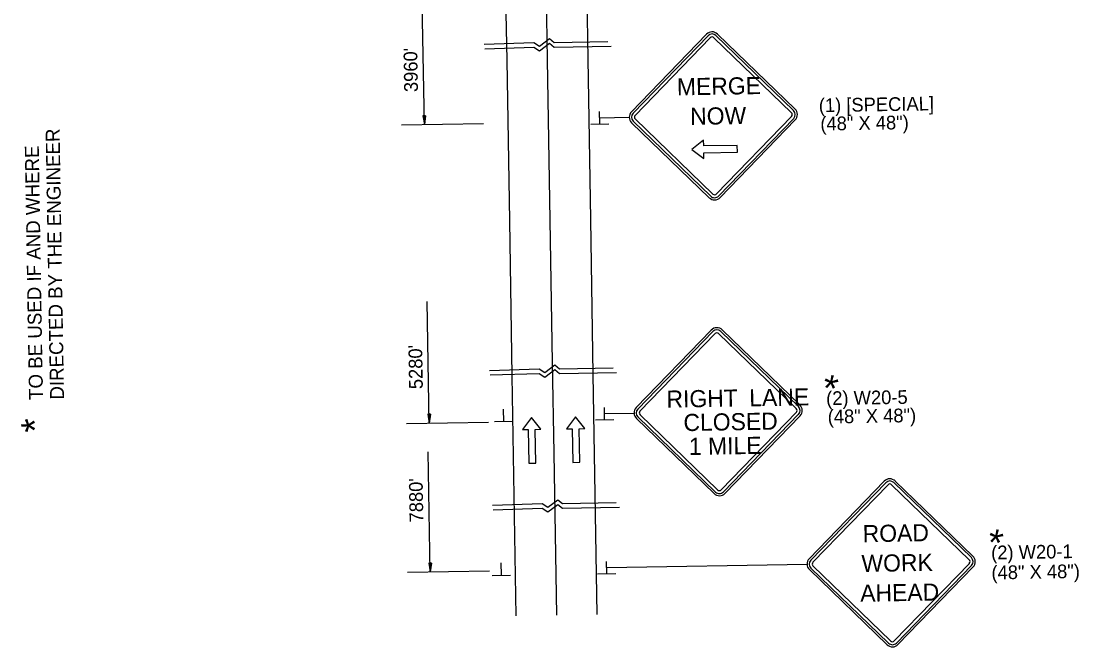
# Model space of a CAD drawing. Extents: x 1676639 to 1677883, y 226447 to 231777.
# Drawn here: x 1676908.3 to 1677371.1, y 228417.4 to 228691.4 of the extents above; entities that cross this region are included whole.
import ezdxf

# ---------------------------------------------------------------- set-up
doc = ezdxf.new("R2010")
doc.units = 0
for name, color, linetype in [('Default', 7, 'Continuous'), ('P_TC_Signs_Temporary', 7, 'Continuous'), ('R_Annotation', 7, 'Continuous'), ('R_MOT', 7, 'Continuous')]:
    doc.layers.add(name, color=color, linetype=linetype)

msp = doc.modelspace()

# ---------------------------------------------------------------- linework, layer by layer
at = {"layer": 'Default'}
for p, q in [((1677156.36, 228674.93), (1677155.09, 228751.27)), ((1677120.9, 228674.34), (1677119.65, 228749.75)), ((1677138.63, 228674.64), (1677137.37, 228750.51)), ((1677084.73, 228646.15), (1677083.84, 228699.37)), ((1677122.07, 228603.97), (1677120.9, 228674.34)), ((1677139.8, 228604.26), (1677138.63, 228674.64)), ((1677157.53, 228604.56), (1677156.36, 228674.93)), ((1677085.24, 228649.98), (1677084.09, 228649.97)), ((1677084.09, 228649.97), (1677084.73, 228646.15)), ((1677084.19, 228649.97), (1677084.72, 228646.79)), ((1677084.28, 228649.97), (1677084.71, 228647.45)), ((1677084.38, 228649.97), (1677084.7, 228648.08)), ((1677084.48, 228649.97), (1677084.68, 228648.73)), ((1677084.57, 228649.97), (1677084.67, 228649.37)), ((1677084.75, 228649.98), (1677084.67, 228649.37)), ((1677084.85, 228649.98), (1677084.68, 228648.73)), ((1677084.95, 228649.98), (1677084.7, 228648.08)), ((1677085.04, 228649.98), (1677084.71, 228647.45)), ((1677085.14, 228649.98), (1677084.72, 228646.79)), ((1677085.24, 228649.98), (1677084.73, 228646.15)), ((1677161.52, 228646.37), (1677161.43, 228651.81)), ((1677074.74, 228645.98), (1677110.65, 228646.58)), ((1677165.49, 228646.32), (1677157.51, 228646.18)), ((1677123.19, 228536.03), (1677122.07, 228603.97)), ((1677140.83, 228541.87), (1677139.8, 228604.26)), ((1677158.65, 228536.67), (1677157.53, 228604.56)), ((1677086.89, 228515.44), (1677086.01, 228568.67)), ((1677141.49, 228502.17), (1677140.83, 228541.87)), ((1677123.77, 228501.1), (1677123.19, 228536.03)), ((1677159.23, 228501.74), (1677158.65, 228536.67)), ((1677119.49, 228516.1), (1677119.4, 228521.55)), ((1677163.61, 228516.83), (1677163.52, 228522.28)), ((1677076.91, 228515.28), (1677112.82, 228515.87)), ((1677087.4, 228519.28), (1677086.26, 228519.26)), ((1677086.26, 228519.26), (1677086.89, 228515.44)), ((1677086.35, 228519.26), (1677086.88, 228516.08)), ((1677086.45, 228519.26), (1677086.87, 228516.74)), ((1677086.55, 228519.26), (1677086.86, 228517.38)), ((1677086.64, 228519.26), (1677086.85, 228518.03)), ((1677086.74, 228519.27), (1677086.84, 228518.66)), ((1677086.92, 228519.27), (1677086.84, 228518.66)), ((1677087.02, 228519.27), (1677086.85, 228518.03)), ((1677087.12, 228519.27), (1677086.86, 228517.38)), ((1677087.21, 228519.27), (1677086.87, 228516.74)), ((1677087.31, 228519.28), (1677086.88, 228516.08)), ((1677087.4, 228519.28), (1677086.89, 228515.44)), ((1677123.46, 228516.05), (1677115.48, 228515.92)), ((1677167.58, 228516.78), (1677159.6, 228516.65)), ((1677087.29, 228450.25), (1677086.42, 228502.87)), ((1677124.94, 228430.96), (1677123.77, 228501.1)), ((1677142.67, 228431.25), (1677141.49, 228502.17)), ((1677160.4, 228431.55), (1677159.23, 228501.74)), ((1677164.56, 228449.43), (1677164.47, 228454.87)), ((1677077.31, 228450.08), (1677113.22, 228450.68)), ((1677087.81, 228454.08), (1677086.66, 228454.06)), ((1677086.66, 228454.06), (1677087.29, 228450.25)), ((1677086.75, 228454.06), (1677087.28, 228450.89)), ((1677086.85, 228454.06), (1677087.27, 228451.54)), ((1677086.95, 228454.07), (1677087.26, 228452.18)), ((1677087.04, 228454.07), (1677087.25, 228452.83)), ((1677087.14, 228454.07), (1677087.24, 228453.47)), ((1677087.32, 228454.07), (1677087.24, 228453.47)), ((1677087.42, 228454.07), (1677087.25, 228452.83)), ((1677087.52, 228454.08), (1677087.26, 228452.18)), ((1677087.61, 228454.08), (1677087.27, 228451.54)), ((1677087.71, 228454.08), (1677087.28, 228450.89)), ((1677087.81, 228454.08), (1677087.29, 228450.25)), ((1677118.48, 228448.76), (1677118.39, 228454.21)), ((1677122.45, 228448.71), (1677114.47, 228448.58)), ((1677168.53, 228449.37), (1677160.56, 228449.24))]:
    msp.add_line(p, q, dxfattribs=at)
for points in [[(1677110.9, 228681.36), (1677132.63, 228682.05), (1677135.12, 228680.44), (1677139.48, 228683.74), (1677141.55, 228682.07), (1677164.97, 228682.46)], [(1677111.13, 228679.33), (1677132.58, 228680.01), (1677135.07, 228678.4), (1677139.43, 228681.7), (1677141.5, 228680.03), (1677166.44, 228680.44)], [(1677113.27, 228538.49), (1677135, 228539.18), (1677137.49, 228537.57), (1677141.85, 228540.87), (1677143.92, 228539.2), (1677167.34, 228539.59)], [(1677113.5, 228536.46), (1677134.95, 228537.14), (1677137.44, 228535.53), (1677141.8, 228538.83), (1677143.86, 228537.16), (1677168.81, 228537.57)], [(1677114.59, 228479.49), (1677136.31, 228480.18), (1677138.81, 228478.57), (1677143.17, 228481.87), (1677145.23, 228480.2), (1677168.66, 228480.59)], [(1677114.82, 228477.46), (1677136.26, 228478.15), (1677138.75, 228476.53), (1677143.12, 228479.83), (1677145.18, 228478.17), (1677170.12, 228478.57)]]:
    msp.add_lwpolyline(points, dxfattribs=at)
at = {"layer": 'P_TC_Signs_Temporary'}
for p, q in [((1677175.35, 228651.71), (1677208.21, 228685.67)), ((1677176.03, 228651.06), (1677208.88, 228685.02)), ((1677176.97, 228650.14), (1677209.82, 228684.1)), ((1677211.41, 228684.13), (1677245.37, 228651.28)), ((1677212.33, 228685.07), (1677246.29, 228652.22)), ((1677212.98, 228685.75), (1677246.94, 228652.89)), ((1677245.4, 228649.69), (1677212.55, 228615.73)), ((1677209.39, 228614.08), (1677175.43, 228646.93)), ((1677210.04, 228614.76), (1677176.08, 228647.61)), ((1677210.96, 228615.7), (1677177, 228648.55)), ((1677246.34, 228648.77), (1677213.49, 228614.81)), ((1677247.02, 228648.12), (1677214.16, 228614.16)), ((1677177.44, 228522.17), (1677210.29, 228556.13)), ((1677178.12, 228521.52), (1677210.97, 228555.48)), ((1677179.06, 228520.61), (1677211.91, 228554.57)), ((1677213.5, 228554.59), (1677247.46, 228521.74)), ((1677214.42, 228555.54), (1677248.38, 228522.69)), ((1677215.07, 228556.21), (1677249.03, 228523.36)), ((1677247.49, 228520.15), (1677214.64, 228486.19)), ((1677211.48, 228484.55), (1677177.52, 228517.4)), ((1677212.13, 228485.22), (1677178.17, 228518.07)), ((1677213.05, 228486.16), (1677179.09, 228519.02)), ((1677248.43, 228519.24), (1677215.58, 228485.28)), ((1677249.11, 228518.59), (1677216.25, 228484.63)), ((1677253.12, 228456.01), (1677285.98, 228489.97)), ((1677253.8, 228455.35), (1677286.65, 228489.31)), ((1677254.74, 228454.44), (1677287.59, 228488.4)), ((1677289.18, 228488.43), (1677323.14, 228455.57)), ((1677290.1, 228489.37), (1677324.06, 228456.52)), ((1677290.75, 228490.04), (1677324.71, 228457.19)), ((1677287.16, 228418.38), (1677253.2, 228451.23)), ((1677287.82, 228419.05), (1677253.86, 228451.91)), ((1677288.73, 228420), (1677254.77, 228452.85)), ((1677323.17, 228453.98), (1677290.32, 228420.02)), ((1677324.11, 228453.07), (1677291.26, 228419.11)), ((1677324.79, 228452.42), (1677291.94, 228418.46))]:
    msp.add_line(p, q, dxfattribs=at)
for centre, radius, start, end in [((1677210.63, 228683.32), 3.38, 45.9497, 135.9497), ((1677210.63, 228683.32), 2.44, 45.9497, 135.9497), ((1677210.63, 228683.32), 1.13, 45.9497, 135.9497), ((1677177.78, 228649.36), 3.38, 135.9497, 225.9497), ((1677177.78, 228649.36), 2.44, 135.9497, 225.9497), ((1677177.78, 228649.36), 1.12, 135.9497, 225.9497), ((1677244.59, 228650.47), 1.12, 315.9497, 45.9497), ((1677244.59, 228650.47), 2.44, 315.9497, 45.9497), ((1677244.59, 228650.47), 3.38, 315.9497, 45.9497), ((1677211.74, 228616.51), 3.38, 225.9497, 315.9497), ((1677211.74, 228616.51), 2.44, 225.9497, 315.9497), ((1677211.74, 228616.51), 1.13, 225.9497, 315.9497), ((1677212.72, 228553.79), 3.38, 45.9497, 135.9497), ((1677212.72, 228553.79), 2.44, 45.9497, 135.9497), ((1677212.72, 228553.79), 1.13, 45.9497, 135.9497), ((1677179.87, 228519.83), 3.38, 135.9497, 225.9497), ((1677179.87, 228519.83), 2.44, 135.9497, 225.9497), ((1677179.87, 228519.83), 1.12, 135.9497, 225.9497), ((1677246.68, 228520.93), 1.12, 315.9497, 45.9497), ((1677246.68, 228520.93), 2.44, 315.9497, 45.9497), ((1677246.68, 228520.93), 3.38, 315.9497, 45.9497), ((1677288.4, 228487.62), 3.38, 45.9497, 135.9497), ((1677288.4, 228487.62), 2.44, 45.9497, 135.9497), ((1677288.4, 228487.62), 1.13, 45.9497, 135.9497), ((1677213.83, 228486.97), 3.38, 225.9497, 315.9497), ((1677213.83, 228486.97), 2.44, 225.9497, 315.9497), ((1677213.83, 228486.97), 1.13, 225.9497, 315.9497), ((1677255.55, 228453.66), 3.38, 135.9497, 225.9497), ((1677255.55, 228453.66), 2.44, 135.9497, 225.9497), ((1677322.36, 228454.77), 1.12, 315.9497, 45.9497), ((1677322.36, 228454.77), 2.44, 315.9497, 45.9497), ((1677322.36, 228454.77), 3.38, 315.9497, 45.9497), ((1677255.55, 228453.66), 1.12, 135.9497, 225.9497), ((1677289.51, 228420.81), 3.38, 225.9497, 315.9497), ((1677289.51, 228420.81), 2.44, 225.9497, 315.9497), ((1677289.51, 228420.81), 1.13, 225.9497, 315.9497)]:
    msp.add_arc(centre, radius, start, end, dxfattribs=at)
at = {"layer": 'R_Annotation'}
for p, q in [((1677161.48, 228649.09), (1677174.4, 228649.3)), ((1677163.57, 228519.56), (1677176.49, 228519.77)), ((1677164.52, 228452.15), (1677252.18, 228453.6)), ((1677164.52, 228452.15), (1677252.18, 228453.6))]:
    msp.add_line(p, q, dxfattribs=at)
at = {"layer": 'R_MOT'}
for points in [[(1677206.9, 228639.23), (1677201.78, 228635.15), (1677207.04, 228631.23), (1677207, 228633.73), (1677221.71, 228633.98), (1677221.66, 228636.98), (1677206.95, 228636.73)], [(1677135.68, 228512.67), (1677131.6, 228517.8), (1677127.69, 228512.54), (1677130.19, 228512.58), (1677130.44, 228497.87), (1677133.44, 228497.92), (1677133.18, 228512.63)], [(1677154.95, 228512.99), (1677150.86, 228518.12), (1677146.95, 228512.85), (1677149.45, 228512.9), (1677149.7, 228498.19), (1677152.7, 228498.24), (1677152.45, 228512.95)]]:
    msp.add_lwpolyline(points, close=True, dxfattribs=at)

# ---------------------------------------------------------------- texts
at = {"layer": 'Default'}
for s, p in [("3960'", (1677081.93, 228660.38)), ("5280'", (1677084.07, 228530.31)), ("7880'", (1677084.29, 228471.96))]:
    msp.add_text(s, height=6, rotation=90.9497, dxfattribs=at).set_placement(p)
at = {"layer": 'P_TC_Signs_Temporary'}
for s, p in [('MERGE', (1677195.28, 228658.86)), ('NOW', (1677201.08, 228645.94)), ('RIGHT\u2002LANE', (1677190.72, 228522.13)), ('CLOSED', (1677198.16, 228511.88)), ('1 MILE', (1677200.53, 228501.42)), (' ROAD ', (1677273.78, 228463.18)), ('WORK', (1677276.03, 228450.19)), (' AHEAD ', (1677272.7, 228437.11))]:
    msp.add_text(s, height=7.5, rotation=0.9497, dxfattribs=at).set_placement(p)
at = {"layer": 'R_Annotation'}
for s, height, rotation, p in [('(1) [SPECIAL]', 6, 0.9497, (1677257.36, 228651.51)), ('(48" X 48")', 6, 0.9497, (1677258.03, 228643.47)), ('DIRECTED BY THE ENGINEER', 6.1199, 90.9497, (1676927.12, 228525.74)), ('TO BE USED IF AND WHERE ', 6.1199, 90.9497, (1676917.89, 228525.59)), ('*', 12, 135.9497, (1677271.09, 228537.47)), ('(2) W20-5', 6, 0.9497, (1677260.57, 228523.26)), ('(48" X 48")', 6, 0.9497, (1677261.25, 228515.21)), ('*', 12, 90.9497, (1676920.39, 228511.39)), ('*', 12, 135.9497, (1677343.28, 228469.91)), ('(2) W20-1', 6, 0.9497, (1677332.76, 228455.7)), ('(48" X 48")', 6, 0.9497, (1677332.9, 228446.96))]:
    msp.add_text(s, height=height, rotation=rotation, dxfattribs=at).set_placement(p)

doc.saveas('drawing.dxf')
